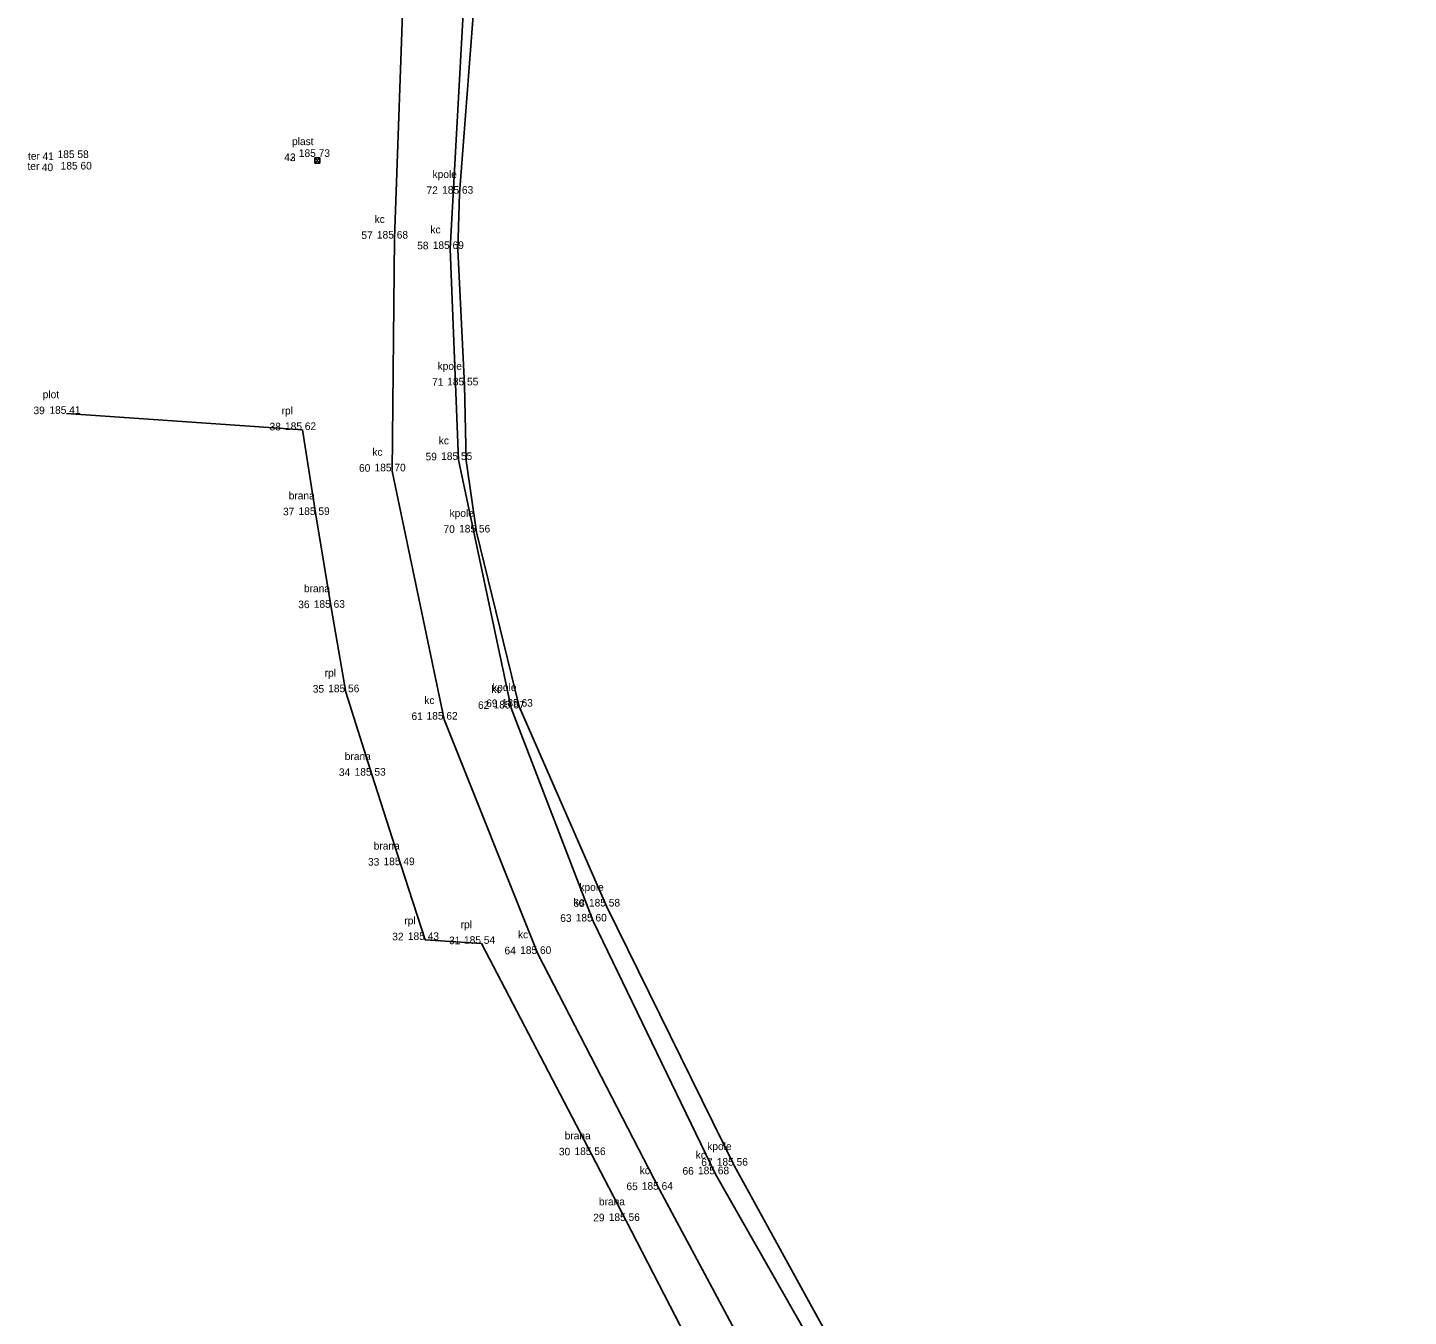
# Model space of a CAD drawing. Extents: x -598527 to -598215, y -1172822 to -1172560.
# Drawn here: x -598526.8 to -598472.4, y -1172770.6 to -1172719.8 of the extents above; entities that cross this region are included whole.
import ezdxf

# ---------------------------------------------------------------- set-up
doc = ezdxf.new("R2010")
doc.units = 0
for name, color, linetype in [('Body', 7, 'Continuous'), ('Body čísla', 7, 'Continuous'), ('Kody', 7, 'Continuous'), ('Kraj pole', 7, 'Continuous'), ('PATTERN_CLASS', 7, 'Continuous'), ('Ploty', 7, 'Continuous'), ('Výšky', 7, 'Continuous')]:
    doc.layers.add(name, color=color, linetype=linetype)

msp = doc.modelspace()

# ---------------------------------------------------------------- linework, layer by layer
at = {"layer": 'Body'}
for p, q in [((-598524.96, -1172724.96), (-598524.96, -1172724.96)), ((-598524.88, -1172724.98), (-598524.88, -1172724.98)), ((-598515.41, -1172725), (-598515.41, -1172725)), ((-598515.41, -1172725), (-598515.41, -1172725)), ((-598509.8, -1172726.3), (-598509.8, -1172726.3)), ((-598512.37, -1172728.07), (-598512.37, -1172728.07)), ((-598510.17, -1172728.48), (-598510.17, -1172728.48)), ((-598509.6, -1172733.86), (-598509.6, -1172733.86)), ((-598525.3, -1172734.98), (-598525.3, -1172734.98)), ((-598515.99, -1172735.62), (-598515.99, -1172735.62)), ((-598509.84, -1172736.8), (-598509.84, -1172736.8)), ((-598512.46, -1172737.25), (-598512.46, -1172737.25)), ((-598515.46, -1172738.97), (-598515.46, -1172738.97)), ((-598509.13, -1172739.66), (-598509.13, -1172739.66)), ((-598514.86, -1172742.63), (-598514.86, -1172742.63)), ((-598514.29, -1172745.96), (-598514.29, -1172745.96)), ((-598507.77, -1172746.6), (-598507.77, -1172746.6)), ((-598507.45, -1172746.53), (-598507.45, -1172746.53)), ((-598510.41, -1172747.04), (-598510.41, -1172747.04)), ((-598513.25, -1172749.25), (-598513.25, -1172749.25)), ((-598512.11, -1172752.78), (-598512.11, -1172752.78)), ((-598504.01, -1172754.41), (-598504.01, -1172754.41)), ((-598504.53, -1172755), (-598504.53, -1172755)), ((-598511.15, -1172755.73), (-598511.15, -1172755.73)), ((-598508.93, -1172755.88), (-598508.93, -1172755.88)), ((-598506.72, -1172756.28), (-598506.72, -1172756.28)), ((-598504.58, -1172764.21), (-598504.58, -1172764.21)), ((-598498.97, -1172764.63), (-598498.97, -1172764.63)), ((-598499.71, -1172764.97), (-598499.71, -1172764.97)), ((-598501.92, -1172765.58), (-598501.92, -1172765.58)), ((-598503.23, -1172766.81), (-598503.23, -1172766.81))]:
    msp.add_line(p, q, dxfattribs=at)
at = {"layer": 'Kraj pole'}
for p, q in [((-598509.13, -1172739.66), (-598507.45, -1172746.53)), ((-598507.45, -1172746.53), (-598504.01, -1172754.41)), ((-598504.01, -1172754.41), (-598498.97, -1172764.63)), ((-598498.97, -1172764.63), (-598488.16, -1172784.31))]:
    msp.add_line(p, q, dxfattribs=at)
for points in [[(-598508.73, -1172715.1), (-598509.129, -1172717.565), (-598509.8, -1172726.3)], [(-598509.8, -1172726.3), (-598509.869, -1172728.507), (-598509.6, -1172733.86)]]:
    msp.add_lwpolyline(points, dxfattribs=at)
at = {"layer": 'PATTERN_CLASS'}
for p, q in [((-598515.51, -1172725.1), (-598515.31, -1172724.9)), ((-598515.51, -1172724.9), (-598515.31, -1172725.1))]:
    msp.add_line(p, q, dxfattribs=at)
for points in [[(-598472.39, -1172818.45), (-598479.4, -1172804.1), (-598488.6, -1172784.48), (-598499.71, -1172764.97), (-598504.53, -1172755), (-598507.77, -1172746.6), (-598509.84, -1172736.8), (-598510.17, -1172728.48), (-598509.56, -1172717.51), (-598507.9, -1172705.69)], [(-598474.23, -1172819.49), (-598481.46, -1172805), (-598491.03, -1172785.9), (-598501.92, -1172765.58), (-598506.72, -1172756.28), (-598510.41, -1172747.04), (-598512.46, -1172737.25), (-598512.37, -1172728.07), (-598511.98, -1172717.34)], [(-598509.6, -1172733.86), (-598509.534, -1172736.829), (-598509.13, -1172739.66)]]:
    msp.add_lwpolyline(points, dxfattribs=at)
msp.add_lwpolyline([(-598515.51, -1172725.1), (-598515.31, -1172725.1), (-598515.31, -1172724.9), (-598515.51, -1172724.9)], close=True, dxfattribs=at)
at = {"layer": 'Ploty'}
for p, q in [((-598515.99, -1172735.62), (-598525.3, -1172734.98)), ((-598515.46, -1172738.97), (-598515.99, -1172735.62)), ((-598514.86, -1172742.63), (-598515.46, -1172738.97)), ((-598514.29, -1172745.96), (-598514.86, -1172742.63)), ((-598513.25, -1172749.25), (-598514.29, -1172745.96)), ((-598512.11, -1172752.78), (-598513.25, -1172749.25)), ((-598511.15, -1172755.73), (-598512.11, -1172752.78)), ((-598508.93, -1172755.88), (-598511.15, -1172755.73)), ((-598504.58, -1172764.21), (-598508.93, -1172755.88)), ((-598503.23, -1172766.81), (-598504.58, -1172764.21)), ((-598500.28, -1172772.53), (-598503.23, -1172766.81))]:
    msp.add_line(p, q, dxfattribs=at)

# ---------------------------------------------------------------- texts
at = {"layer": 'Body čísla'}
for s, p in [('41', (-598526.244, -1172724.983)), ('42', (-598516.713, -1172725.023)), ('43', (-598516.71, -1172725.023)), ('40', (-598526.27, -1172725.418)), ('72', (-598511.103, -1172726.323)), ('57', (-598513.671, -1172728.093)), ('58', (-598511.471, -1172728.503)), ('71', (-598510.884, -1172733.883)), ('39', (-598526.599, -1172735.003)), ('38', (-598517.291, -1172735.643)), ('59', (-598511.139, -1172736.823)), ('60', (-598513.763, -1172737.273)), ('37', (-598516.761, -1172738.993)), ('70', (-598510.433, -1172739.683)), ('36', (-598516.16, -1172742.653)), ('35', (-598515.588, -1172745.983)), ('62', (-598509.073, -1172746.623)), ('69', (-598508.749, -1172746.553)), ('61', (-598511.694, -1172747.063)), ('34', (-598514.557, -1172749.273)), ('33', (-598513.41, -1172752.803)), ('68', (-598505.311, -1172754.433)), ('63', (-598505.83, -1172755.023)), ('32', (-598512.453, -1172755.753)), ('31', (-598510.214, -1172755.903)), ('64', (-598508.027, -1172756.303)), ('30', (-598505.883, -1172764.233)), ('66', (-598501.01, -1172764.993)), ('67', (-598500.271, -1172764.653)), ('65', (-598503.218, -1172765.603)), ('29', (-598504.529, -1172766.833))]:
    msp.add_text(s, height=0.3, dxfattribs=at).set_placement(p)
at = {"layer": 'Kody'}
for s, p in [('plast', (-598516.404, -1172724.393)), ('ter', (-598526.836, -1172725.369)), ('ter', (-598526.815, -1172724.97)), ('kpole', (-598510.864, -1172725.693)), ('kc', (-598513.148, -1172727.463)), ('kc', (-598510.948, -1172727.873)), ('kpole', (-598510.664, -1172733.253)), ('plot', (-598526.235, -1172734.373)), ('rpl', (-598516.816, -1172735.013)), ('kc', (-598510.618, -1172736.193)), ('kc', (-598513.238, -1172736.643)), ('brana', (-598516.535, -1172738.363)), ('kpole', (-598510.194, -1172739.053)), ('brana', (-598515.935, -1172742.023)), ('rpl', (-598515.116, -1172745.353)), ('kc', (-598508.548, -1172745.993)), ('kpole', (-598508.514, -1172745.923)), ('kc', (-598511.188, -1172746.433)), ('brana', (-598514.325, -1172748.643)), ('brana', (-598513.185, -1172752.173)), ('kpole', (-598505.074, -1172753.803)), ('kc', (-598505.308, -1172754.393)), ('rpl', (-598511.976, -1172755.123)), ('rpl', (-598509.756, -1172755.273)), ('kc', (-598507.498, -1172755.673)), ('brana', (-598505.655, -1172763.603)), ('kpole', (-598500.034, -1172764.023)), ('kc', (-598500.488, -1172764.363)), ('kc', (-598502.698, -1172764.973)), ('brana', (-598504.305, -1172766.203))]:
    msp.add_text(s, height=0.3, dxfattribs=at).set_placement(p)
at = {"layer": 'PATTERN_CLASS'}
msp.add_text('plast', height=0.3, dxfattribs=at).set_placement((-598516.404, -1172724.393))
at = {"layer": 'Výšky'}
for s, p in [('185 73', (-598516.136, -1172724.857)), ('185 58', (-598525.648, -1172724.902)), ('185 60', (-598525.527, -1172725.355)), ('185 63', (-598510.487, -1172726.308)), ('185 68', (-598513.058, -1172728.078)), ('185 69', (-598510.857, -1172728.488)), ('185 55', (-598510.286, -1172733.868)), ('185 41', (-598525.971, -1172734.988)), ('185 62', (-598516.681, -1172735.628)), ('185 55', (-598510.526, -1172736.808)), ('185 70', (-598513.15, -1172737.258)), ('185 59', (-598516.147, -1172738.978)), ('185 56', (-598509.818, -1172739.668)), ('185 63', (-598515.547, -1172742.638)), ('185 56', (-598514.978, -1172745.968)), ('185 67', (-598508.459, -1172746.608)), ('185 63', (-598508.137, -1172746.538)), ('185 62', (-598511.101, -1172747.048)), ('185 53', (-598513.937, -1172749.258)), ('185 49', (-598512.797, -1172752.788)), ('185 58', (-598504.698, -1172754.418)), ('185 60', (-598505.22, -1172755.008)), ('185 43', (-598511.837, -1172755.738)), ('185 54', (-598509.624, -1172755.888)), ('185 60', (-598507.41, -1172756.288)), ('185 56', (-598505.268, -1172764.218)), ('185 68', (-598500.398, -1172764.978)), ('185 56', (-598499.658, -1172764.638)), ('185 64', (-598502.614, -1172765.588)), ('185 56', (-598503.918, -1172766.818))]:
    msp.add_text(s, height=0.3, dxfattribs=at).set_placement(p)

doc.saveas('drawing.dxf')
